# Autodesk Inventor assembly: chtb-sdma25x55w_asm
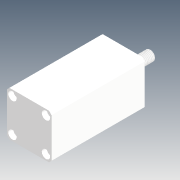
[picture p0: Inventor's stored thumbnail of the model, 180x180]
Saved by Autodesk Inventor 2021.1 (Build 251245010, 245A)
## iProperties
Company: Microsoft
Created: 2018-05
Part Number: chtb-sdma25x55w_asm
Description: STEP AP214
Document SubType Name: Assembly
Designer: user
Title: chtb-sdma25x55w_asm.STEP
Author: Windows
Revision Number: ÈÎºÎ
Sending System: SolidWorks 2015
Preprocessor: SwSTEP 2.0
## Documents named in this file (4)
- D:\Vault_2016\Projekty\Clamptek\Hydraulic\CHTB\CHTB-25\Inventor\chtb-sdma25x55w\chtb-sdma25x55w_asm.iam
- D:\Vault_2016\Projekty\Clamptek\Hydraulic\CHTB\CHTB-25\Inventor\chtb-sdma25x55w\CHTB-25QG.ipt
- D:\Vault_2016\Projekty\Clamptek\Hydraulic\CHTB\CHTB-25\Inventor\chtb-sdma25x55w\CHTB-SDMA25X55NBT.ipt
- D:\Vault_2016\Projekty\Clamptek\Hydraulic\CHTB\CHTB-25\Inventor\chtb-sdma25x55w\CHTB-SDMA25X55WHSG.ipt
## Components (3 placed, 3 different names)
1. CHTB-25QG_1
2. CHTB-SDMA25X55NBT_2
3. CHTB-SDMA25X55WHSG_3
